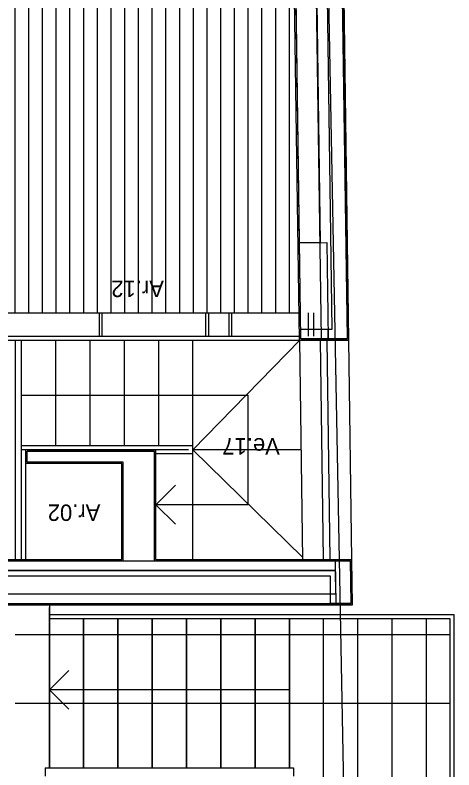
# Model space of a CAD drawing. Extents: x 1248 to 1356, y -443 to -224.
# Drawn here: x 1348.94 to 1352.14, y -239.41 to -233.9 of the extents above; entities that cross this region are included whole.
import ezdxf

# ---------------------------------------------------------------- set-up
doc = ezdxf.new("R2010")
doc.units = 0
for name, color, linetype in [('corte', 7, 'Continuous'), ('estereoctomias', 7, 'Continuous'), ('Level 1', 7, 'Continuous'), ('Level 10', 7, 'Continuous'), ('Level 13', 7, 'Continuous'), ('Level 2', 7, 'Continuous'), ('Level 40', 7, 'Continuous'), ('revestimentos', 7, 'Continuous'), ('vermelhos-cont', 7, 'Continuous')]:
    doc.layers.add(name, color=color, linetype=linetype)

msp = doc.modelspace()

# ---------------------------------------------------------------- linework, layer by layer
at = {"layer": 'corte'}
for p, q in [((1351.2839, -238.194), (1351.2796, -237.884)), ((1351.3939, -238.194), (1351.3896, -237.884))]:
    msp.add_line(p, q, dxfattribs=at)
for points in [[(1351.2172, -235.5613), (1351.227, -236.2612), (1351.0269, -236.264), (1351.0172, -235.5641)], [(1351.2445, -237.9963), (1348.1934, -237.9963), (1348.1934, -238.1963), (1351.2445, -238.1963)]]:
    msp.add_lwpolyline(points, close=True, dxfattribs=at)
at = {"layer": 'estereoctomias'}
for points in [[(1351.3669, -236.264), (1351.227, -236.264), (1351.226, -236.194), (1351.2559, -236.194), (1351.198, -232.044), (1349.9745, -232.044), (1349.9745, -232.114), (1350.9689, -232.114), (1350.9711, -232.264), (1349.9045, -232.264), (1349.9045, -231.934), (1351.3065, -231.934), (1351.3669, -236.264)], [(1351.1281, -232.7648), (1351.1671, -235.562), (1351.0171, -235.5641), (1350.9782, -232.7669)], [(1351.2805, -237.954), (1347.9287, -237.954), (1347.9287, -238.124), (1347.8587, -238.124), (1347.8587, -237.884), (1349.7307, -237.884), (1349.7307, -237.164), (1349.0306, -237.164), (1349.0306, -237.084), (1349.9607, -237.084), (1349.9607, -237.884), (1351.3896, -237.884), (1351.3939, -238.194), (1351.2445, -238.194), (1351.2445, -238.124), (1351.2829, -238.124)]]:
    msp.add_lwpolyline(points, close=True, dxfattribs=at)
at = {"layer": 'Level 1'}
for p, q in [((1351.3669, -236.264), (1351.3065, -231.934)), ((1351.2559, -236.194), (1351.198, -232.044)), ((1351.0269, -236.264), (1350.9711, -232.264)), ((1351.1769, -236.2619), (1351.1281, -232.7648)), ((1349.9607, -237.084), (1349.0306, -237.084)), ((1349.0306, -237.164), (1349.0306, -237.084)), ((1349.9607, -237.884), (1349.9607, -237.084)), ((1349.7307, -237.164), (1349.0306, -237.164)), ((1349.7307, -237.884), (1349.7307, -237.164)), ((1347.8587, -237.884), (1351.3896, -237.884)), ((1347.8587, -237.884), (1351.2695, -237.884)), ((1347.9287, -237.954), (1351.2805, -237.954)), ((1347.9287, -238.124), (1351.2829, -238.124)), ((1347.5287, -238.194), (1351.3939, -238.194))]:
    msp.add_line(p, q, dxfattribs=at)
for points in [[(1351.0269, -236.194), (1351.2559, -236.194)], [(1351.0269, -236.264), (1351.3669, -236.264)]]:
    msp.add_lwpolyline(points, dxfattribs=at)
at = {"layer": 'Level 10'}
for p, q in [((1348.9437, -236.074), (1348.9437, -232.274)), ((1349.0437, -236.074), (1349.0437, -232.274)), ((1349.1437, -236.074), (1349.1437, -232.274)), ((1349.2437, -236.074), (1349.2437, -232.274)), ((1349.3437, -236.074), (1349.3437, -232.274)), ((1349.4437, -236.074), (1349.4437, -232.274)), ((1349.5437, -236.074), (1349.5437, -232.274)), ((1349.6437, -236.074), (1349.6437, -232.274)), ((1349.7437, -236.074), (1349.7437, -232.274)), ((1349.8437, -236.074), (1349.8437, -232.274)), ((1349.9437, -236.074), (1349.9437, -232.274)), ((1350.0437, -236.074), (1350.0437, -232.274)), ((1350.1437, -236.074), (1350.1437, -232.274)), ((1350.2437, -236.074), (1350.2437, -232.274)), ((1350.3437, -236.074), (1350.3437, -232.274)), ((1350.4437, -236.074), (1350.4437, -232.274)), ((1350.5437, -236.074), (1350.5437, -232.274)), ((1350.6437, -236.074), (1350.6437, -232.274)), ((1350.7437, -236.074), (1350.7437, -232.274)), ((1350.8437, -236.074), (1350.8437, -232.274)), ((1350.9437, -236.074), (1350.9437, -232.274)), ((1348.9437, -236.274), (1348.9437, -237.874)), ((1349.1933, -239.394), (1349.1933, -238.224)), ((1349.4433, -239.394), (1349.4433, -238.304)), ((1349.6933, -239.394), (1349.6933, -238.304)), ((1349.9433, -239.394), (1349.9433, -238.304)), ((1350.1933, -239.394), (1350.1933, -238.304)), ((1350.4433, -239.394), (1350.4433, -238.304)), ((1350.6933, -239.394), (1350.6933, -238.304)), ((1350.9433, -239.394), (1350.9433, -238.304)), ((1351.1933, -240.544), (1351.1933, -238.304)), ((1351.4433, -240.544), (1351.4433, -238.304)), ((1351.6933, -240.544), (1351.6933, -238.304)), ((1351.9433, -240.544), (1351.9433, -238.304)), ((1352.1133, -238.424), (1348.9433, -238.424)), ((1352.1133, -238.924), (1348.9433, -238.924))]:
    msp.add_line(p, q, dxfattribs=at)
at = {"layer": 'Level 13'}
for p, q in [((1348.3117, -236.074), (1351.0142, -236.074)), ((1349.5584, -236.244), (1349.5584, -236.074)), ((1349.5784, -236.244), (1349.5784, -236.074)), ((1350.3351, -236.244), (1350.3351, -236.074)), ((1350.3551, -236.244), (1350.3551, -236.074)), ((1350.5051, -236.244), (1350.5051, -236.074)), ((1350.5251, -236.244), (1350.5251, -236.074)), ((1351.0818, -236.244), (1351.0818, -236.074)), ((1351.1218, -236.244), (1351.1218, -236.074)), ((1348.3117, -236.244), (1351.0166, -236.244)), ((1348.3117, -236.274), (1351.017, -236.274)), ((1348.9906, -237.874), (1348.9906, -237.074)), ((1349.0206, -237.074), (1348.9906, -237.074)), ((1349.0206, -237.874), (1349.0206, -237.074))]:
    msp.add_line(p, q, dxfattribs=at)
at = {"layer": 'Level 2'}
for p, q in [((1348.9906, -237.074), (1348.9906, -236.274)), ((1349.2406, -237.044), (1349.2406, -236.274)), ((1349.4906, -237.044), (1349.4906, -236.274)), ((1349.7406, -237.044), (1349.7406, -236.274)), ((1349.9906, -237.044), (1349.9906, -236.274)), ((1350.2406, -237.074), (1351.0191, -236.274)), ((1350.2406, -237.044), (1350.2406, -236.274)), ((1351.017, -236.274), (1351.0394, -237.874)), ((1351.1671, -236.274), (1351.1894, -237.872)), ((1351.2171, -236.274), (1351.2394, -237.8713)), ((1351.3994, -237.874), (1351.3771, -236.274)), ((1348.9906, -236.674), (1350.6439, -236.674)), ((1350.6439, -237.474), (1350.6439, -236.674)), ((1350.2406, -237.044), (1348.9906, -237.044)), ((1350.2406, -237.104), (1350.2406, -237.044)), ((1350.2083, -237.074), (1348.9906, -237.074)), ((1350.2406, -237.104), (1349.9707, -237.104)), ((1350.2406, -237.074), (1351.0413, -237.859)), ((1351.0303, -237.074), (1350.2406, -237.074)), ((1350.2406, -237.874), (1350.2406, -237.104)), ((1350.1121, -237.3326), (1349.9707, -237.474)), ((1350.1121, -237.6154), (1349.9707, -237.474)), ((1350.6439, -237.474), (1349.9707, -237.474)), ((1349.1933, -238.204), (1349.1933, -239.394)), ((1349.1933, -238.274), (1352.1433, -238.274)), ((1352.1433, -238.274), (1352.1433, -240.574)), ((1349.1933, -238.304), (1352.1133, -238.304)), ((1349.4433, -238.304), (1349.4433, -239.394)), ((1349.6933, -238.304), (1349.6933, -239.394)), ((1349.9433, -238.304), (1349.9433, -239.394)), ((1350.1933, -238.304), (1350.1933, -239.394)), ((1350.4433, -238.304), (1350.4433, -239.394)), ((1350.6933, -238.304), (1350.6933, -239.394)), ((1350.9433, -238.304), (1350.9433, -239.394)), ((1352.1133, -238.304), (1352.1133, -240.544)), ((1349.3347, -238.6826), (1349.1933, -238.824)), ((1350.9433, -238.824), (1349.1933, -238.824)), ((1349.3347, -238.9654), (1349.1933, -238.824)), ((1349.1633, -239.394), (1350.9733, -239.394)), ((1349.1633, -239.394), (1349.1633, -239.454)), ((1350.9733, -239.394), (1350.9733, -239.454))]:
    msp.add_line(p, q, dxfattribs=at)
at = {"layer": 'revestimentos'}
for p, q in [((1351.3771, -236.274), (1351.3164, -231.924)), ((1351.017, -236.274), (1350.9612, -232.274)), ((1349.9707, -237.074), (1349.0007, -237.074)), ((1349.0206, -237.174), (1349.0206, -237.074)), ((1349.9707, -237.874), (1349.9707, -237.074)), ((1349.7207, -237.174), (1349.0206, -237.174)), ((1349.7207, -237.874), (1349.7207, -237.174)), ((1347.8487, -237.874), (1349.7207, -237.874)), ((1349.9707, -237.874), (1351.3994, -237.874)), ((1351.404, -238.204), (1351.3994, -237.874)), ((1347.5387, -238.204), (1351.404, -238.204))]:
    msp.add_line(p, q, dxfattribs=at)
msp.add_lwpolyline([(1351.017, -236.274), (1351.3771, -236.274)], dxfattribs=at)
at = {"layer": 'vermelhos-cont'}
msp.add_line((1351.1483, -229.6198), (1351.553, -250.7923), dxfattribs=at)

# ---------------------------------------------------------------- texts
at = {"layer": 'Level 40'}
for s, p in [('Ar.12', (1350.0289, -235.8393)), ('Ve.17', (1350.874, -236.988)), ('Ar.02', (1349.5651, -237.4726))]:
    msp.add_text(s, height=0.12, rotation=180, dxfattribs=at).set_placement(p)

doc.saveas('drawing.dxf')
